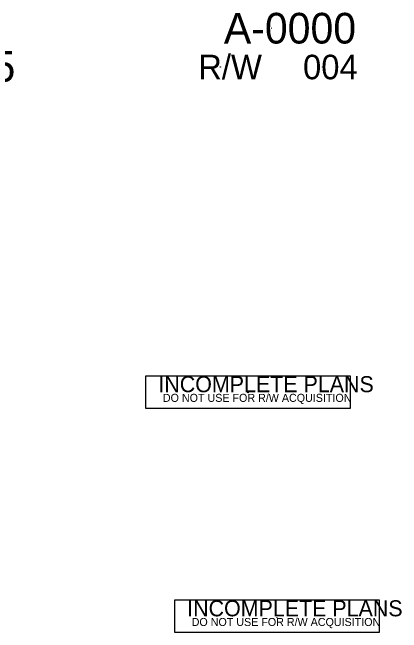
# Model space of a CAD drawing. Extents: x -0.71 to 3.09, y 0 to 1.8.
# Drawn here: x 2.771 to 3.089, y 1.292 to 1.797 of the extents above; entities that cross this region are included whole.
import ezdxf

# ---------------------------------------------------------------- set-up
doc = ezdxf.new("R2010")
doc.units = 0
for name, color, linetype in [('P_NCDOT_Horizontal_Alignment', 7, 'Continuous'), ('P_NCDOT_Horizontal_Alignment_Station_Major_Label', 7, 'Continuous'), ('P_NCDOT_Horizontal_Alignment_Tick_Small', 7, 'Continuous'), ('Sheet Plan CELL', 7, 'Continuous')]:
    doc.layers.add(name, color=color, linetype=linetype)

msp = doc.modelspace()

# ---------------------------------------------------------------- linework, layer by layer
at = {"layer": 'P_NCDOT_Horizontal_Alignment'}
for centre in [(2.98259, 1.78436), (2.94092, 1.75276), (3.02426, 1.75276)]:
    msp.add_circle(centre, 0.0001, dxfattribs=at)
at = {"layer": 'P_NCDOT_Horizontal_Alignment_Station_Major_Label'}
for points in [[(2.88021, 1.47464), (2.88021, 1.50128), (3.04688, 1.50128), (3.04688, 1.47464)], [(2.90371, 1.29208), (2.90371, 1.31872), (3.07038, 1.31872), (3.07038, 1.29208)]]:
    msp.add_lwpolyline(points, close=True, dxfattribs=at)
at = {"layer": 'Sheet Plan CELL'}
for centre in [(2.9635, 1.48748), (2.987, 1.30451)]:
    msp.add_circle(centre, 0.0001, dxfattribs=at)

# ---------------------------------------------------------------- texts
at = {"layer": 'P_NCDOT_Horizontal_Alignment'}
for s, height, p in [('A-0000', 0.025, (2.94381, 1.77186)), ('R/W', 0.02, (2.92284, 1.74276)), ('004', 0.02, (3.00833, 1.74276))]:
    msp.add_text(s, height=height, dxfattribs=at).set_placement(p)
at = {"layer": 'P_NCDOT_Horizontal_Alignment_Station_Major_Label'}
for s, height, p in [('INCOMPLETE PLANS', 0.0130613, (2.89036, 1.4879)), ('DO NOT USE FOR R/W ACQUISITION', 0.0065306, (2.89405, 1.48002)), ('INCOMPLETE PLANS', 0.0130613, (2.91386, 1.30534)), ('DO NOT USE FOR R/W ACQUISITION', 0.0065306, (2.91754, 1.29746))]:
    msp.add_text(s, height=height, dxfattribs=at).set_placement(p)
at = {"layer": 'P_NCDOT_Horizontal_Alignment_Tick_Small'}
msp.add_text('HB-0035', height=0.025, dxfattribs=at).set_placement((2.64177, 1.74068))

doc.saveas('drawing.dxf')
